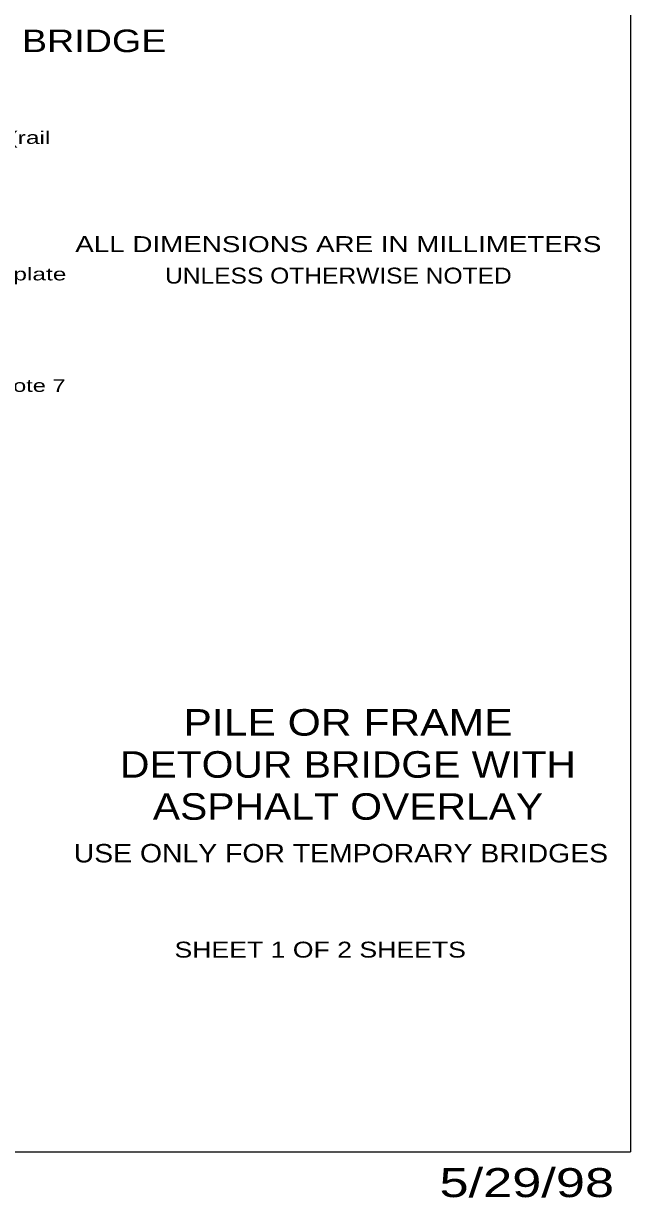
# Model space of a CAD drawing. Extents: x 13426 to 15509, y -9298 to -5111.
# Drawn here: x 15446.3 to 15509.2, y -5596.8 to -5475.2 of the extents above; entities that cross this region are included whole.
import ezdxf
from ezdxf.enums import TextEntityAlignment as Align

# ---------------------------------------------------------------- set-up
doc = ezdxf.new("R2010")
doc.units = 0
doc.header["$LTSCALE"] = 0.52
for name, color, linetype, lineweight in [('1', 7, 'Continuous', 13), ('20', 7, 'Continuous', 13), ('30', 7, 'Continuous', 25)]:
    doc.layers.add(name, color=color, linetype=linetype, lineweight=lineweight)
doc.layers.add('19', color=7, linetype='Continuous')
doc.layers.add('32', color=7, linetype='Continuous')

msp = doc.modelspace()

# ---------------------------------------------------------------- linework, layer by layer
at = {"layer": '30'}
for p in [(15509.151, -5379.846), (15181.119, -5592.065)]:
    msp.add_line(p, (15509.151, -5592.065), dxfattribs=at)

# ---------------------------------------------------------------- texts
at = {"layer": '1', "width": 1.35}
msp.add_text('5/29/98', height=3, dxfattribs=at).set_placement((15498.4185, -5596.755), align=Align.CENTER)
at = {"layer": '19', "width": 1.45}
for s, p in [('M12x180 mm Bolt (rail', (15423.763, -5487.698)), ('75x75x13 mm Bearing plate', (15419.218, -5501.831))]:
    msp.add_text(s, height=1.307, dxfattribs=at).set_placement(p)
at = {"layer": '19'}
for s, width, p in [('ALL DIMENSIONS ARE IN MILLIMETERS', 1.3, (15478.9175, -5498.903)), ('UNLESS OTHERWISE NOTED', 1.15, (15478.9175, -5502.163))]:
    msp.add_text(s, height=1.653, dxfattribs=dict(at, width=width)).set_placement(p, align=Align.CENTER)
at = {"layer": '20'}
for s, height, width, p in [('TYPICAL SECTION-TWO LANE BRIDGE', 2.333, 1.25, (15424.934, -5478.191)), ('USE ONLY FOR TEMPORARY BRIDGES', 1.909, 1.15, (15479.18, -5562.099)), ('SHEET 1 OF 2 SHEETS', 1.648, 1.25, (15477.0355, -5571.956))]:
    msp.add_text(s, height=height, dxfattribs=dict(at, width=width)).set_placement(p, align=Align.CENTER)
at = {"layer": '20', "width": 1.4}
msp.add_text('See Note 7', height=1.307, dxfattribs=at).set_placement((15438.45, -5513.375))
at = {"layer": '32'}
for s, width, p in [('PILE OR FRAME', 1.2, (15479.913, -5548.972)), ('DETOUR BRIDGE WITH', 1.15, (15479.9125, -5553.327)), ('ASPHALT OVERLAY', 1.15, (15479.913, -5557.682))]:
    msp.add_text(s, height=2.748, dxfattribs=dict(at, width=width)).set_placement(p, align=Align.CENTER)

doc.saveas('drawing.dxf')
